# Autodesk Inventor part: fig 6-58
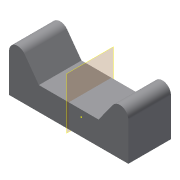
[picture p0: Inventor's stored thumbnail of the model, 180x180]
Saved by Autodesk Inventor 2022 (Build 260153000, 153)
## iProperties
Created: 2011-07
Part Number: fig 6-58
Material: Generic
Document SubType Name: Modeling
Designer: CadCim
Density: 1 g/cm^3
Appearance: Default
Author: CadCim
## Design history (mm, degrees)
sketch "Sketch1"
  geometry: 1 further point
sketch "Sketch2"
  geometry: L1 (3, -4)-(17, -4); L2 (17, -4)-(17, 7); L3 (17, 7)-(14, 7); L4 (14, 7)-(10, 1.5); L5 (10, 1.5)-(3, 1.5); L6 (3, -4)-(-11, -4); L7 (-11, -4)-(-11, 7); L8 (-11, 7)-(-8, 7); L9 (-8, 7)-(-4, 1.5); L10 (-4, 1.5)-(3, 1.5); 1 further point
  constraints: 20 end point, 2 parallel, 1 perpendicular
extrude "Extrusion1" new body sketch "Sketch2" distance "d0" = 10; taper "d1" = 0 deg
fillet "Fillet1" dims "d2" = 2
workplane "Work Plane1"
mirror "Mirror1"
body "Solid1"
